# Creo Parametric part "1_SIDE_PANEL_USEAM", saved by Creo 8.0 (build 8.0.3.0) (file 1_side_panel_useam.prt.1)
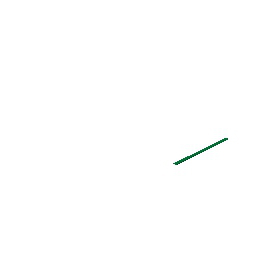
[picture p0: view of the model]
Units: millimeter Newton Second (mmNs); MM, TONNE, SECS

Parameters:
  SMT_DFLT_BEND_REL_LENGTH_TYPE = "Through All"

Other parameters: SMT_THICKNESS, SMT_PART_BEND_ALLOWANCE_FACTOR, SMT_DFLT_BEND_RADIUS, SMT_DFLT_BEND_ANGLE, SMT_DFLT_CRNR_REL_WIDTH, SMT_DFLT_CRNR_REL_DEPTH, SMT_DFLT_BEND_REL_WIDTH, SMT_DFLT_BEND_REL_DEPTH, SMT_DFLT_BEND_REL_LENGTH, SMT_DFLT_BEND_REL_ANGLE, SMT_GAP, SMT_DFLT_EDGE_TREA_WIDTH, SMT_DFLT_MITER_CUT_WIDTH, SMT_DFLT_MITER_CUT_OFFSET

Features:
  1. datum plane "DTM1"
  2. datum plane "DTM2"
  3. datum plane "DTM3"
  4. coordinate system
  5. datum plane "DTM9"
  6. datum plane "DTM10"

Other named items: CS0

Layers: 0_ALL_AXIS, 0_ALL_CSYS, 0_ALL_CURVES, 0_ALL_PLANES, 0_ALL_POINTS, 0_ALL_SURFS, 1_SIDE_PANEL_USEAM

Surfaces: 30 plane, 8 cylinder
